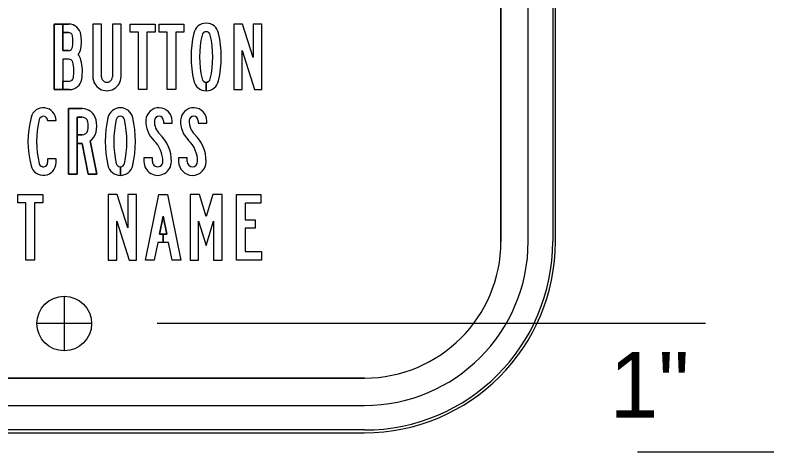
# Model space of a CAD drawing. Extents: x 0 to 770, y 0 to 495.
# Drawn here: x 89.89 to 130.42, y 204.96 to 228.27 of the extents above; entities that cross this region are included whole.
import ezdxf

# ---------------------------------------------------------------- set-up
doc = ezdxf.new("R2010")
doc.units = 0
for name, color, linetype in [('Default', 7, 'Continuous'), ('GSBWFill', 7, 'Continuous'), ('GSColorFill', 7, 'Continuous'), ('GSDims', 7, 'Continuous'), ('GSOutline', 7, 'Continuous'), ('IndexDetail_0', 7, 'Continuous')]:
    doc.layers.add(name, color=color, linetype=linetype)

msp = doc.modelspace()

# ---------------------------------------------------------------- linework, layer by layer
at = {"layer": 'GSBWFill'}
for p, q in [((115.839, 283.258), (115.839, 216.184)), ((117.297, 216.184), (117.297, 283.258)), ((118.755, 216.184), (118.755, 283.258)), ((100.092, 224.234), (100.092, 224.689)), ((100.092, 224.689), (100.092, 224.234)), ((91.622, 222.645), (92.077, 222.645)), ((93.459, 221.424), (93.197, 221.424)), ((91.622, 220.593), (91.622, 220.4)), ((95.507, 219.718), (95.507, 220.173)), ((95.507, 220.173), (95.507, 219.718)), ((108.548, 208.893), (76.484, 208.893)), ((76.484, 207.435), (108.548, 207.435)), ((76.469, 205.977), (108.548, 205.977))]:
    msp.add_line(p, q, dxfattribs=at)
for points in [[(92.756, 225.922), (92.428, 225.922), (92.428, 224.295), (91.973, 224.295), (91.973, 227.795), (92.428, 227.795), (92.428, 226.377), (92.739, 226.377)], [(92.741, 227.34), (92.428, 227.34), (92.428, 227.795), (92.741, 227.795)], [(94.492, 224.986), (94.492, 227.795), (94.037, 227.795), (94.037, 224.986)], [(95.542, 224.986), (95.542, 227.795), (95.087, 227.795), (95.087, 224.986)], [(92.789, 224.295), (92.428, 224.295), (92.428, 224.75), (92.789, 224.75)], [(93.459, 222.824), (93.197, 222.824), (93.197, 219.779), (92.742, 219.779), (92.742, 223.279), (93.459, 223.279)], [(97.816, 222.628), (97.816, 222.505), (98.271, 222.505), (98.271, 222.628)], [(99.671, 222.628), (99.671, 222.505), (100.126, 222.505), (100.126, 222.628)], [(93.197, 221.424), (93.197, 221.879), (93.459, 221.879)], [(93.897, 221.56), (94.247, 219.779), (93.783, 219.779), (93.46, 221.424)], [(92.077, 220.4), (92.077, 220.593), (91.622, 220.593)], [(97.221, 220.453), (97.221, 220.645), (96.766, 220.645), (96.766, 220.453)], [(99.076, 220.453), (99.076, 220.645), (98.621, 220.645), (98.621, 220.453)]]:
    msp.add_lwpolyline(points, dxfattribs=at)
for points in [[(97.362, 227.357), (96.925, 227.357), (96.925, 224.295), (96.47, 224.295), (96.47, 227.357), (96.032, 227.357), (96.032, 227.795), (97.362, 227.795)], [(98.902, 227.357), (98.464, 227.357), (98.464, 224.295), (98.009, 224.295), (98.009, 227.357), (97.572, 227.357), (97.572, 227.795), (98.902, 227.795)], [(102.681, 224.295), (103.066, 224.295), (103.066, 227.795), (102.611, 227.795), (102.611, 226.01), (102.041, 227.795), (101.561, 227.795), (101.561, 224.295), (102.016, 224.295), (102.016, 226.377)], [(91.357, 218.259), (90.919, 218.259), (90.919, 215.197), (90.464, 215.197), (90.464, 218.259), (90.027, 218.259), (90.027, 218.696), (91.357, 218.696)], [(95.976, 215.197), (96.361, 215.197), (96.361, 218.696), (95.906, 218.696), (95.906, 216.912), (95.336, 218.696), (94.856, 218.696), (94.856, 215.197), (95.311, 215.197), (95.311, 217.279)], [(97.796, 216.579), (97.993, 216.579), (97.796, 217.541), (97.599, 216.579), (97.796, 216.579), (97.796, 216.124), (97.506, 216.124), (97.315, 215.197), (96.851, 215.197), (97.568, 218.696), (98.023, 218.696), (98.741, 215.197), (98.276, 215.197), (98.086, 216.124), (97.796, 216.124)], [(100.491, 215.197), (100.946, 215.197), (100.946, 218.696), (100.449, 218.696), (100.088, 217.518), (99.727, 218.696), (99.231, 218.696), (99.231, 215.197), (99.686, 215.197), (99.686, 217.279), (100.088, 215.967), (100.491, 217.279)], [(103.01, 218.696), (103.01, 218.241), (102.17, 218.241), (102.17, 217.349), (102.713, 217.349), (102.713, 216.894), (102.17, 216.894), (102.17, 215.652), (103.045, 215.652), (103.045, 215.197), (101.715, 215.197), (101.715, 218.696)]]:
    msp.add_lwpolyline(points, close=True, dxfattribs=at)
for centre, radius, start, end in [((99.426, 222.628), 0.7, 0, 177.3048), ((100.125, 222.595), 1.4, 177.3048, 226.0638), ((100.125, 222.595), 0.945, 177.3048, 226.0638), ((99.426, 222.628), 0.245, 0, 177.3048), ((98.061, 220.453), 2.03, 0, 46.0638), ((98.061, 220.453), 1.575, 0, 46.0638), ((99.356, 220.453), 0.735, 180, 0), ((99.356, 220.453), 0.28, 180, 0), ((108.548, 216.184), 8.749, 270, 0), ((108.548, 216.184), 7.291, 270, 0), ((108.548, 216.184), 10.207, 270, 0)]:
    msp.add_arc(centre, radius, start, end, dxfattribs=at)
for centre, major_axis, ratio, start_param, end_param in [((100.092, 227.161), (0, 0.682), 0.999998, 4.929767, 7.636603), ((92.741, 227.13), (0, 0.665), 0.999991, 4.854375, 6.283185), ((92.741, 227.13), (0, 0.21), 0.999991, 4.854375, 6.283185), ((90.905, 226.867), (0, 2.065), 0.999991, 4.560866, 4.854375), ((90.905, 226.867), (0, 2.52), 0.999991, 4.560866, 4.854375), ((105.174, 226.039), (0, 5.887), 0.999998, 1.353418, 1.788175), ((105.174, 226.039), (0, 5.432), 0.999998, 1.353418, 1.788175), ((100.092, 227.161), (0, 0.227), 0.999998, 4.929767, 7.636603), ((95.009, 226.039), (0, 5.432), 0.999998, 4.495011, 4.929767), ((95.009, 226.039), (0, 5.887), 0.999998, 4.495011, 4.929767), ((92.739, 226.587), (0, 0.21), 0.999991, 3.141593, 4.560866), ((92.739, 226.587), (0, 0.665), 0.999991, 4.013727, 4.560866), ((92.756, 225.713), (0, 0.21), 0.999991, 4.960201, 6.283185), ((92.756, 225.713), (0, 0.665), 0.999991, 4.960201, 5.4501), ((90.958, 225.258), (0, 2.52), 0.999991, 4.551316, 4.960201), ((90.958, 225.258), (0, 2.065), 0.999991, 4.551316, 4.960201), ((94.79, 224.986), (0, 0.752), 0.999998, 1.570796, 4.712389), ((94.79, 224.986), (0, 0.297), 0.999998, 1.570796, 4.712389), ((92.789, 224.96), (0, 0.21), 0.999991, 3.141593, 4.551316), ((92.789, 224.96), (0, 0.665), 0.999991, 3.141593, 4.551316), ((100.092, 224.916), (0, 0.682), 0.999998, 1.788175, 3.141593), ((100.092, 224.916), (0, 0.227), 0.999998, 1.788175, 3.141593), ((100.092, 224.916), (0, 0.227), 0.999998, 3.142362, 4.495011), ((100.092, 224.916), (0, 0.682), 0.999998, 3.141849, 4.495011), ((91.395, 222.645), (0, 0.682), 0.999988, 4.712389, 7.605847), ((93.459, 222.509), (0, 0.77), 0.999998, 4.939332, 6.283185), ((95.507, 222.645), (0, 0.682), 0.999991, 4.929767, 7.636603), ((97.571, 222.628), (0, 0.7), 0.999998, 4.712389, 7.806942), ((95.825, 221.523), (0, 5.253), 0.999988, 1.322662, 1.818931), ((95.825, 221.523), (0, 4.798), 0.999988, 1.322662, 1.818931), ((91.395, 222.645), (0, 0.227), 0.999988, 4.712389, 7.605847), ((93.459, 222.509), (0, 0.315), 0.999998, 4.939332, 6.283185), ((92.777, 222.351), (0, 1.015), 0.999998, 4.485446, 4.939332), ((92.777, 222.351), (0, 1.47), 0.999998, 4.485446, 4.939332), ((100.589, 221.523), (0, 5.887), 0.999991, 1.353418, 1.788175), ((100.589, 221.523), (0, 5.432), 0.999991, 1.353418, 1.788175), ((95.507, 222.645), (0, 0.227), 0.999991, 4.929767, 7.636603), ((90.424, 221.523), (0, 5.432), 0.999991, 4.495011, 4.929767), ((90.424, 221.523), (0, 5.887), 0.999991, 4.495011, 4.929767), ((98.27, 222.595), (0, 1.4), 0.999998, 1.523757, 2.374761), ((98.27, 222.595), (0, 0.945), 0.999998, 1.523757, 2.374761), ((97.571, 222.628), (0, 0.245), 0.999998, 4.712389, 7.806942), ((93.459, 222.194), (0, 0.315), 0.999998, 3.141593, 4.485446), ((93.459, 222.194), (0, 0.77), 0.999998, 3.746596, 4.485446), ((96.206, 220.453), (0, 2.03), 0.999998, 4.712389, 5.516353), ((93.459, 222.194), (0, 0.77), 0.999998, 3.141593, 3.143023), ((96.206, 220.453), (0, 1.575), 0.999998, 4.712389, 5.516353), ((91.395, 220.4), (0, 0.682), 0.999988, 1.818931, 4.712389), ((91.395, 220.4), (0, 0.227), 0.999988, 1.818931, 4.712389), ((95.507, 220.4), (0, 0.682), 0.999991, 1.788175, 3.141593), ((95.507, 220.4), (0, 0.227), 0.999991, 1.788175, 3.141593), ((95.507, 220.4), (0, 0.227), 0.999991, 3.142362, 4.495011), ((95.507, 220.4), (0, 0.682), 0.999991, 3.141849, 4.495011), ((97.501, 220.453), (0, 0.735), 0.999998, 1.570796, 4.712389), ((97.501, 220.453), (0, 0.28), 0.999998, 1.570796, 4.712389)]:
    msp.add_ellipse(centre, major_axis=major_axis, ratio=ratio, start_param=start_param, end_param=end_param, dxfattribs=at)
at = {"layer": 'GSColorFill'}
for p, q in [((115.839, 283.258), (115.839, 216.184)), ((117.297, 216.184), (117.297, 283.258)), ((118.609, 283.258), (118.609, 216.184)), ((118.755, 216.184), (118.755, 283.258)), ((118.755, 216.184), (118.755, 283.258)), ((100.092, 224.234), (100.092, 224.689)), ((100.092, 224.689), (100.092, 224.234)), ((91.622, 222.645), (92.077, 222.645)), ((93.459, 221.424), (93.197, 221.424)), ((91.622, 220.593), (91.622, 220.4)), ((95.507, 219.718), (95.507, 220.173)), ((95.507, 220.173), (95.507, 219.718)), ((108.548, 208.893), (76.484, 208.893)), ((76.484, 207.435), (108.548, 207.435)), ((76.469, 205.977), (108.548, 205.977)), ((108.548, 206.123), (76.47, 206.123)), ((76.47, 205.977), (108.548, 205.977))]:
    msp.add_line(p, q, dxfattribs=at)
for points in [[(92.756, 225.922), (92.428, 225.922), (92.428, 224.295), (91.973, 224.295), (91.973, 227.795), (92.428, 227.795), (92.428, 226.377), (92.739, 226.377)], [(92.741, 227.34), (92.428, 227.34), (92.428, 227.795), (92.741, 227.795)], [(94.492, 224.986), (94.492, 227.795), (94.037, 227.795), (94.037, 224.986)], [(95.542, 224.986), (95.542, 227.795), (95.087, 227.795), (95.087, 224.986)], [(92.789, 224.295), (92.428, 224.295), (92.428, 224.75), (92.789, 224.75)], [(93.459, 222.824), (93.197, 222.824), (93.197, 219.779), (92.742, 219.779), (92.742, 223.279), (93.459, 223.279)], [(97.816, 222.628), (97.816, 222.505), (98.271, 222.505), (98.271, 222.628)], [(99.671, 222.628), (99.671, 222.505), (100.126, 222.505), (100.126, 222.628)], [(93.197, 221.424), (93.197, 221.879), (93.459, 221.879)], [(93.897, 221.56), (94.247, 219.779), (93.783, 219.779), (93.46, 221.424)], [(92.077, 220.4), (92.077, 220.593), (91.622, 220.593)], [(97.221, 220.453), (97.221, 220.645), (96.766, 220.645), (96.766, 220.453)], [(99.076, 220.453), (99.076, 220.645), (98.621, 220.645), (98.621, 220.453)]]:
    msp.add_lwpolyline(points, dxfattribs=at)
for points in [[(97.362, 227.357), (96.925, 227.357), (96.925, 224.295), (96.47, 224.295), (96.47, 227.357), (96.032, 227.357), (96.032, 227.795), (97.362, 227.795)], [(98.902, 227.357), (98.464, 227.357), (98.464, 224.295), (98.009, 224.295), (98.009, 227.357), (97.572, 227.357), (97.572, 227.795), (98.902, 227.795)], [(102.681, 224.295), (103.066, 224.295), (103.066, 227.795), (102.611, 227.795), (102.611, 226.01), (102.041, 227.795), (101.561, 227.795), (101.561, 224.295), (102.016, 224.295), (102.016, 226.377)], [(91.357, 218.259), (90.919, 218.259), (90.919, 215.197), (90.464, 215.197), (90.464, 218.259), (90.027, 218.259), (90.027, 218.696), (91.357, 218.696)], [(95.976, 215.197), (96.361, 215.197), (96.361, 218.696), (95.906, 218.696), (95.906, 216.912), (95.336, 218.696), (94.856, 218.696), (94.856, 215.197), (95.311, 215.197), (95.311, 217.279)], [(97.796, 216.579), (97.993, 216.579), (97.796, 217.541), (97.599, 216.579), (97.796, 216.579), (97.796, 216.124), (97.506, 216.124), (97.315, 215.197), (96.851, 215.197), (97.568, 218.696), (98.023, 218.696), (98.741, 215.197), (98.276, 215.197), (98.086, 216.124), (97.796, 216.124)], [(100.491, 215.197), (100.946, 215.197), (100.946, 218.696), (100.449, 218.696), (100.088, 217.518), (99.727, 218.696), (99.231, 218.696), (99.231, 215.197), (99.686, 215.197), (99.686, 217.279), (100.088, 215.967), (100.491, 217.279)], [(103.01, 218.696), (103.01, 218.241), (102.17, 218.241), (102.17, 217.349), (102.713, 217.349), (102.713, 216.894), (102.17, 216.894), (102.17, 215.652), (103.045, 215.652), (103.045, 215.197), (101.715, 215.197), (101.715, 218.696)]]:
    msp.add_lwpolyline(points, close=True, dxfattribs=at)
for centre, radius, start, end in [((99.426, 222.628), 0.7, 0, 177.3048), ((100.125, 222.595), 1.4, 177.3048, 226.0638), ((100.125, 222.595), 0.945, 177.3048, 226.0638), ((99.426, 222.628), 0.245, 0, 177.3048), ((98.061, 220.453), 2.03, 0, 46.0638), ((98.061, 220.453), 1.575, 0, 46.0638), ((99.356, 220.453), 0.735, 180, 0), ((99.356, 220.453), 0.28, 180, 0), ((108.548, 216.184), 10.207, 270, 0), ((108.548, 216.184), 8.749, 270, 0), ((108.548, 216.184), 7.291, 270, 0), ((108.548, 216.184), 10.207, 270, 0), ((108.548, 216.184), 10.061, 270, 0)]:
    msp.add_arc(centre, radius, start, end, dxfattribs=at)
for centre, major_axis, ratio, start_param, end_param in [((100.092, 227.161), (0, 0.682), 0.999998, 4.929767, 7.636603), ((92.741, 227.13), (0, 0.665), 0.999991, 4.854375, 6.283185), ((92.741, 227.13), (0, 0.21), 0.999991, 4.854375, 6.283185), ((90.905, 226.867), (0, 2.065), 0.999991, 4.560866, 4.854375), ((90.905, 226.867), (0, 2.52), 0.999991, 4.560866, 4.854375), ((105.174, 226.039), (0, 5.887), 0.999998, 1.353418, 1.788175), ((105.174, 226.039), (0, 5.432), 0.999998, 1.353418, 1.788175), ((100.092, 227.161), (0, 0.227), 0.999998, 4.929767, 7.636603), ((95.009, 226.039), (0, 5.432), 0.999998, 4.495011, 4.929767), ((95.009, 226.039), (0, 5.887), 0.999998, 4.495011, 4.929767), ((92.739, 226.587), (0, 0.21), 0.999991, 3.141593, 4.560866), ((92.739, 226.587), (0, 0.665), 0.999991, 4.013727, 4.560866), ((92.756, 225.713), (0, 0.21), 0.999991, 4.960201, 6.283185), ((92.756, 225.713), (0, 0.665), 0.999991, 4.960201, 5.4501), ((90.958, 225.258), (0, 2.52), 0.999991, 4.551316, 4.960201), ((90.958, 225.258), (0, 2.065), 0.999991, 4.551316, 4.960201), ((94.79, 224.986), (0, 0.752), 0.999998, 1.570796, 4.712389), ((94.79, 224.986), (0, 0.297), 0.999998, 1.570796, 4.712389), ((92.789, 224.96), (0, 0.21), 0.999991, 3.141593, 4.551316), ((92.789, 224.96), (0, 0.665), 0.999991, 3.141593, 4.551316), ((100.092, 224.916), (0, 0.682), 0.999998, 1.788175, 3.141593), ((100.092, 224.916), (0, 0.227), 0.999998, 1.788175, 3.141593), ((100.092, 224.916), (0, 0.227), 0.999998, 3.142362, 4.495011), ((100.092, 224.916), (0, 0.682), 0.999998, 3.141849, 4.495011), ((91.395, 222.645), (0, 0.682), 0.999988, 4.712389, 7.605847), ((93.459, 222.509), (0, 0.77), 0.999998, 4.939332, 6.283185), ((95.507, 222.645), (0, 0.682), 0.999991, 4.929767, 7.636603), ((97.571, 222.628), (0, 0.7), 0.999998, 4.712389, 7.806942), ((95.825, 221.523), (0, 5.253), 0.999988, 1.322662, 1.818931), ((95.825, 221.523), (0, 4.798), 0.999988, 1.322662, 1.818931), ((91.395, 222.645), (0, 0.227), 0.999988, 4.712389, 7.605847), ((93.459, 222.509), (0, 0.315), 0.999998, 4.939332, 6.283185), ((92.777, 222.351), (0, 1.015), 0.999998, 4.485446, 4.939332), ((92.777, 222.351), (0, 1.47), 0.999998, 4.485446, 4.939332), ((100.589, 221.523), (0, 5.887), 0.999991, 1.353418, 1.788175), ((100.589, 221.523), (0, 5.432), 0.999991, 1.353418, 1.788175), ((95.507, 222.645), (0, 0.227), 0.999991, 4.929767, 7.636603), ((90.424, 221.523), (0, 5.432), 0.999991, 4.495011, 4.929767), ((90.424, 221.523), (0, 5.887), 0.999991, 4.495011, 4.929767), ((98.27, 222.595), (0, 1.4), 0.999998, 1.523757, 2.374761), ((98.27, 222.595), (0, 0.945), 0.999998, 1.523757, 2.374761), ((97.571, 222.628), (0, 0.245), 0.999998, 4.712389, 7.806942), ((93.459, 222.194), (0, 0.315), 0.999998, 3.141593, 4.485446), ((93.459, 222.194), (0, 0.77), 0.999998, 3.746596, 4.485446), ((96.206, 220.453), (0, 2.03), 0.999998, 4.712389, 5.516353), ((93.459, 222.194), (0, 0.77), 0.999998, 3.141593, 3.143023), ((96.206, 220.453), (0, 1.575), 0.999998, 4.712389, 5.516353), ((91.395, 220.4), (0, 0.682), 0.999988, 1.818931, 4.712389), ((91.395, 220.4), (0, 0.227), 0.999988, 1.818931, 4.712389), ((95.507, 220.4), (0, 0.682), 0.999991, 1.788175, 3.141593), ((95.507, 220.4), (0, 0.227), 0.999991, 1.788175, 3.141593), ((95.507, 220.4), (0, 0.227), 0.999991, 3.142362, 4.495011), ((95.507, 220.4), (0, 0.682), 0.999991, 3.141849, 4.495011), ((97.501, 220.453), (0, 0.735), 0.999998, 1.570796, 4.712389), ((97.501, 220.453), (0, 0.28), 0.999998, 1.570796, 4.712389)]:
    msp.add_ellipse(centre, major_axis=major_axis, ratio=ratio, start_param=start_param, end_param=end_param, dxfattribs=at)
at = {"layer": 'GSDims'}
msp.add_line((123.13, 204.957), (130.42, 204.957), dxfattribs=at)
at = {"layer": 'GSOutline'}
for p, q in [((115.839, 216.184), (115.839, 283.258)), ((117.297, 216.184), (117.297, 283.258)), ((118.755, 216.184), (118.755, 283.258)), ((92.741, 227.34), (92.741, 227.34)), ((91.622, 222.645), (92.077, 222.645)), ((93.197, 221.424), (93.459, 221.424)), ((91.622, 220.593), (91.622, 220.4)), ((76.469, 208.893), (108.548, 208.893)), ((76.469, 207.435), (108.548, 207.435)), ((76.469, 205.977), (108.548, 205.977))]:
    msp.add_line(p, q, dxfattribs=at)
for points in [[(92.741, 227.795), (91.973, 227.795), (91.973, 224.295), (92.789, 224.295)], [(94.492, 224.986), (94.492, 227.795), (94.037, 227.795), (94.037, 224.986)], [(95.542, 224.986), (95.542, 227.795), (95.087, 227.795), (95.087, 224.986)], [(92.739, 226.377), (92.428, 226.377), (92.428, 227.34), (92.741, 227.34)], [(92.756, 225.922), (92.428, 225.922), (92.428, 224.75), (92.789, 224.75)], [(93.459, 223.279), (92.742, 223.279), (92.742, 219.779), (93.197, 219.779), (93.197, 221.424)], [(93.459, 221.879), (93.197, 221.879), (93.197, 222.824), (93.459, 222.824)], [(97.816, 222.628), (97.816, 222.505), (98.271, 222.505), (98.271, 222.628)], [(99.671, 222.628), (99.671, 222.505), (100.126, 222.505), (100.126, 222.628)], [(93.46, 221.424), (93.783, 219.779), (94.247, 219.779), (93.897, 221.56)], [(92.077, 220.4), (92.077, 220.593), (91.622, 220.593)], [(97.221, 220.453), (97.221, 220.645), (96.766, 220.645), (96.766, 220.453)], [(99.076, 220.453), (99.076, 220.645), (98.621, 220.645), (98.621, 220.453)]]:
    msp.add_lwpolyline(points, dxfattribs=at)
for points in [[(97.362, 227.357), (96.925, 227.357), (96.925, 224.295), (96.47, 224.295), (96.47, 227.357), (96.032, 227.357), (96.032, 227.795), (97.362, 227.795)], [(98.902, 227.357), (98.464, 227.357), (98.464, 224.295), (98.009, 224.295), (98.009, 227.357), (97.572, 227.357), (97.572, 227.795), (98.902, 227.795)], [(102.681, 224.295), (103.066, 224.295), (103.066, 227.795), (102.611, 227.795), (102.611, 226.01), (102.041, 227.795), (101.561, 227.795), (101.561, 224.295), (102.016, 224.295), (102.016, 226.377)], [(91.357, 218.259), (90.919, 218.259), (90.919, 215.197), (90.464, 215.197), (90.464, 218.259), (90.027, 218.259), (90.027, 218.696), (91.357, 218.696)], [(95.976, 215.197), (96.361, 215.197), (96.361, 218.696), (95.906, 218.696), (95.906, 216.912), (95.336, 218.696), (94.856, 218.696), (94.856, 215.197), (95.311, 215.197), (95.311, 217.279)], [(97.315, 215.197), (96.851, 215.197), (97.568, 218.696), (98.023, 218.696), (98.741, 215.197), (98.276, 215.197), (98.086, 216.124), (97.506, 216.124)], [(100.491, 215.197), (100.946, 215.197), (100.946, 218.696), (100.449, 218.696), (100.088, 217.518), (99.727, 218.696), (99.231, 218.696), (99.231, 215.197), (99.686, 215.197), (99.686, 217.279), (100.088, 215.967), (100.491, 217.279)], [(103.01, 218.696), (103.01, 218.241), (102.17, 218.241), (102.17, 217.349), (102.713, 217.349), (102.713, 216.894), (102.17, 216.894), (102.17, 215.652), (103.045, 215.652), (103.045, 215.197), (101.715, 215.197), (101.715, 218.696)], [(97.993, 216.579), (97.599, 216.579), (97.796, 217.541)]]:
    msp.add_lwpolyline(points, close=True, dxfattribs=at)
for centre, radius, start, end in [((99.426, 222.628), 0.7, 0, 177.3048), ((100.125, 222.595), 1.4, 177.3048, 226.0638), ((100.125, 222.595), 0.945, 177.3048, 226.0638), ((99.426, 222.628), 0.245, 0, 177.3048), ((98.061, 220.453), 2.03, 0, 46.0638), ((98.061, 220.453), 1.575, 0, 46.0638), ((99.356, 220.453), 0.735, 180, 0), ((99.356, 220.453), 0.28, 180, 0), ((108.548, 216.184), 8.749, 270, 0), ((108.548, 216.184), 7.291, 270, 0), ((108.548, 216.184), 10.207, 270, 0)]:
    msp.add_arc(centre, radius, start, end, dxfattribs=at)
for centre, major_axis, ratio, start_param, end_param in [((100.092, 227.161), (0, 0.682), 0.999998, 4.929767, 7.636603), ((92.741, 227.13), (0, 0.665), 0.999991, 4.854375, 6.283185), ((92.741, 227.13), (0, 0.21), 0.999991, 4.854375, 6.283185), ((90.905, 226.867), (0, 2.065), 0.999991, 4.560866, 4.854375), ((90.905, 226.867), (0, 2.52), 0.999991, 4.560866, 4.854375), ((105.174, 226.039), (0, 5.887), 0.999998, 1.353418, 1.788175), ((105.174, 226.039), (0, 5.432), 0.999998, 1.353418, 1.788175), ((100.092, 227.161), (0, 0.227), 0.999998, 4.929767, 7.636603), ((95.009, 226.039), (0, 5.432), 0.999998, 4.495011, 4.929767), ((95.009, 226.039), (0, 5.887), 0.999998, 4.495011, 4.929767), ((92.739, 226.587), (0, 0.21), 0.999991, 3.141593, 4.560866), ((92.739, 226.587), (0, 0.665), 0.999991, 4.013727, 4.560866), ((92.756, 225.713), (0, 0.21), 0.999991, 4.960201, 6.283185), ((92.756, 225.713), (0, 0.665), 0.999991, 4.960201, 5.4501), ((90.958, 225.258), (0, 2.52), 0.999991, 4.551316, 4.960201), ((90.958, 225.258), (0, 2.065), 0.999991, 4.551316, 4.960201), ((94.79, 224.986), (0, 0.752), 0.999998, 1.570796, 4.712389), ((94.79, 224.986), (0, 0.297), 0.999998, 1.570796, 4.712389), ((92.789, 224.96), (0, 0.21), 0.999991, 3.141593, 4.551316), ((92.789, 224.96), (0, 0.665), 0.999991, 3.141593, 4.551316), ((100.092, 224.916), (0, 0.682), 0.999998, 1.788175, 4.495011), ((100.092, 224.916), (0, 0.227), 0.999998, 1.788175, 4.495011), ((91.395, 222.645), (0, 0.682), 0.999988, 4.712389, 7.605847), ((93.459, 222.509), (0, 0.77), 0.999998, 4.939332, 6.283185), ((95.507, 222.645), (0, 0.682), 0.999991, 4.929767, 7.636603), ((97.571, 222.628), (0, 0.7), 0.999998, 4.712389, 7.806942), ((95.825, 221.523), (0, 5.253), 0.999988, 1.322662, 1.818931), ((95.825, 221.523), (0, 4.798), 0.999988, 1.322662, 1.818931), ((91.395, 222.645), (0, 0.227), 0.999988, 4.712389, 7.605847), ((93.459, 222.509), (0, 0.315), 0.999998, 4.939332, 6.283185), ((92.777, 222.351), (0, 1.015), 0.999998, 4.485446, 4.939332), ((92.777, 222.351), (0, 1.47), 0.999998, 4.485446, 4.939332), ((100.589, 221.523), (0, 5.887), 0.999991, 1.353418, 1.788175), ((100.589, 221.523), (0, 5.432), 0.999991, 1.353418, 1.788175), ((95.507, 222.645), (0, 0.227), 0.999991, 4.929767, 7.636603), ((90.424, 221.523), (0, 5.432), 0.999991, 4.495011, 4.929767), ((90.424, 221.523), (0, 5.887), 0.999991, 4.495011, 4.929767), ((98.27, 222.595), (0, 1.4), 0.999998, 1.523757, 2.374761), ((98.27, 222.595), (0, 0.945), 0.999998, 1.523757, 2.374761), ((97.571, 222.628), (0, 0.245), 0.999998, 4.712389, 7.806942), ((93.459, 222.194), (0, 0.315), 0.999998, 3.141593, 4.485446), ((93.459, 222.194), (0, 0.77), 0.999998, 3.746596, 4.485446), ((96.206, 220.453), (0, 2.03), 0.999998, 4.712389, 5.516353), ((93.459, 222.194), (0, 0.77), 0.999998, 3.141593, 3.143023), ((96.206, 220.453), (0, 1.575), 0.999998, 4.712389, 5.516353), ((91.395, 220.4), (0, 0.682), 0.999988, 1.818931, 4.712389), ((91.395, 220.4), (0, 0.227), 0.999988, 1.818931, 4.712389), ((95.507, 220.4), (0, 0.682), 0.999991, 1.788175, 4.495011), ((95.507, 220.4), (0, 0.227), 0.999991, 1.788175, 4.495011), ((97.501, 220.453), (0, 0.735), 0.999998, 1.570796, 4.712389), ((97.501, 220.453), (0, 0.28), 0.999998, 1.570796, 4.712389)]:
    msp.add_ellipse(centre, major_axis=major_axis, ratio=ratio, start_param=start_param, end_param=end_param, dxfattribs=at)
at = {"layer": 'IndexDetail_0'}
for p, q in [((92.509, 213.266), (92.509, 210.348)), ((93.968, 211.807), (91.049, 211.807)), ((126.775, 211.807), (97.467, 211.807))]:
    msp.add_line(p, q, dxfattribs=at)
msp.add_circle((92.509, 211.807), 1.459, dxfattribs=at)

# ---------------------------------------------------------------- texts
at = {"layer": 'Default'}
msp.add_text('1"', height=3.5, dxfattribs=at).set_placement((121.646, 206.789))

doc.saveas('drawing.dxf')
